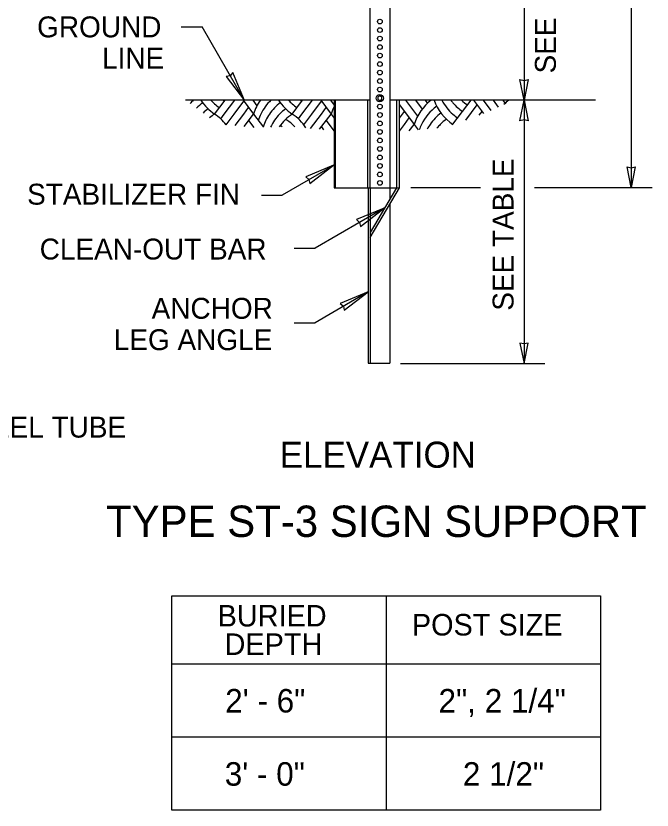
# Model space of a CAD drawing. Extents: x 99862 to 103680, y 99470 to 102076.
# Drawn here: x 101132 to 101618, y 100979 to 101587 of the extents above; entities that cross this region are included whole.
import ezdxf

# ---------------------------------------------------------------- set-up
doc = ezdxf.new("R2010")
doc.units = 0
for name, color, linetype in [('Level 15', 7, 'Continuous'), ('Level 2', 7, 'Continuous'), ('Level 20', 7, 'Continuous'), ('Level 3', 7, 'Continuous'), ('Level 4', 7, 'Continuous'), ('Level 40', 7, 'Continuous'), ('Level 5', 7, 'Continuous'), ('Level 6', 7, 'Continuous')]:
    doc.layers.add(name, color=color, linetype=linetype)

msp = doc.modelspace()

# ---------------------------------------------------------------- linework, layer by layer
at = {"layer": 'Level 15'}
for p, q in [((101258, 101578.2), (101274, 101578.2)), ((101306.5, 101521.91), (101274, 101578.2)), ((101375.06, 101472.43), (101335.38, 101449.51)), ((101319.38, 101449.51), (101335.38, 101449.51)), ((101413.43, 101439.5), (101360.5, 101408.8)), ((101344.5, 101408.8), (101360.5, 101408.8)), ((101400.98, 101375.33), (101360.5, 101351.82)), ((101344.5, 101351.82), (101360.5, 101351.82))]:
    msp.add_line(p, q, dxfattribs=at)
for points in [[(101602.31, 101944.46), (101602.31, 101455.34)], [(101520.31, 101815.74), (101520.31, 101522.09)], [(101520.31, 101522.09), (101520.31, 101320.46)], [(101433.72, 101455.34), (101487.14, 101455.34)], [(101528.31, 101455.34), (101618.31, 101455.34)], [(101425.95, 101320.46), (101536.31, 101320.46)]]:
    msp.add_lwpolyline(points, dxfattribs=at)
for points in [[(101306.5, 101521.91), (101297.67, 101543.17), (101295.61, 101540.77), (101292.5, 101540.19)], [(101520.31, 101522.09), (101517.23, 101537.81), (101520.31, 101537.09), (101523.4, 101537.81)], [(101520.31, 101522.09), (101523.4, 101506.37), (101520.31, 101507.09), (101517.23, 101506.37)], [(101374.65, 101472.39), (101353.39, 101463.56), (101355.8, 101461.5), (101356.37, 101458.39)], [(101602.31, 101455.34), (101599.23, 101471.06), (101602.31, 101470.34), (101605.4, 101471.06)], [(101413.43, 101439.5), (101392.17, 101430.67), (101394.58, 101428.61), (101395.15, 101425.5)], [(101400.98, 101375.33), (101379.71, 101366.5), (101382.12, 101364.45), (101382.7, 101361.33)], [(101520.31, 101320.51), (101523.4, 101336.23), (101520.31, 101335.51), (101517.23, 101336.23)]]:
    msp.add_lwpolyline(points, close=True, dxfattribs=at)
at = {"layer": 'Level 2'}
for points in [[(101402.69, 101522.06), (101402.69, 101660.51)], [(101417.79, 101660.51), (101417.79, 101521.95)], [(101402.69, 101454.42), (101402.69, 101522.09)], [(101417.79, 101521.85), (101417.79, 101454.64)]]:
    msp.add_lwpolyline(points, dxfattribs=at)
msp.add_lwpolyline([(101409.93, 101525.36), (101408.44, 101524.5), (101408.44, 101522.77), (101409.93, 101521.9), (101411.43, 101522.77), (101411.43, 101524.5)], close=True, dxfattribs=at)
msp.add_circle((101409.93, 101523.63), 2.77, dxfattribs=at)
at = {"layer": 'Level 3'}
for p, q in [((101400.98, 101454.91), (101400.98, 101320.78)), ((101402.65, 101454.91), (101402.65, 101320.78)), ((101417.74, 101454.91), (101417.74, 101446.29)), ((101417.74, 101442.33), (101417.74, 101320.78)), ((101400.98, 101320.78), (101402.65, 101320.78)), ((101402.65, 101320.78), (101417.74, 101320.78))]:
    msp.add_line(p, q, dxfattribs=at)
for centre in [(101410.06, 101582.27), (101410.06, 101575.77), (101410.06, 101569.27), (101410.06, 101562.77), (101410.06, 101556.27), (101410.06, 101549.77), (101410.06, 101543.27), (101410.06, 101536.77), (101410.06, 101530.27), (101410.06, 101517.27), (101410.06, 101510.77), (101410.06, 101504.27), (101410.06, 101497.77), (101410.06, 101491.27), (101410.06, 101484.77), (101410.06, 101478.27), (101410.06, 101471.77), (101410.06, 101465.27), (101410.06, 101458.77)]:
    msp.add_circle(centre, 1.8, dxfattribs=at)
at = {"layer": 'Level 4'}
for p, q in [((101375.06, 101522.09), (101375.06, 101454.91)), ((101375.77, 101521.97), (101375.77, 101454.91)), ((101400.88, 101454.91), (101400.88, 101521.97)), ((101422.81, 101522.09), (101422.81, 101454.91)), ((101424.95, 101454.91), (101424.95, 101522.09)), ((101423.82, 101454.91), (101424.95, 101454.91))]:
    msp.add_line(p, q, dxfattribs=at)
for points, degree in [([(101375.06, 101454.91), (101375.42, 101454.91), (101375.77, 101454.91)], 2), ([(101375.77, 101454.91), (101388.32, 101454.91), (101400.88, 101454.91), (101411.84, 101454.91), (101422.81, 101454.91), (101423.32, 101454.91), (101423.82, 101454.91)], 4)]:
    msp.add_open_spline(points, degree=degree, dxfattribs=at)
at = {"layer": 'Level 40'}
for p, q in [((101414.79, 101142.76), (101414.79, 100978.76)), ((101250.79, 101090.76), (101578.79, 101090.76)), ((101250.79, 101034.76), (101578.79, 101034.76))]:
    msp.add_line(p, q, dxfattribs=at)
msp.add_lwpolyline([(101250.79, 101142.76), (101578.79, 101142.76), (101578.79, 100978.76), (101250.79, 100978.76)], close=True, dxfattribs=at)
at = {"layer": 'Level 5'}
for p, q in [((101283.62, 101511.49), (101291.57, 101522.09)), ((101291.04, 101511.49), (101298.99, 101522.09)), ((101298.47, 101511.49), (101305.89, 101521.39)), ((101305.37, 101522.09), (101313.32, 101511.49)), ((101312.79, 101522.09), (101315.99, 101517.82)), ((101343.02, 101511.49), (101350.97, 101522.09)), ((101350.44, 101511.49), (101358.39, 101522.09)), ((101357.87, 101511.49), (101365.29, 101521.39)), ((101364.77, 101522.09), (101372.71, 101511.49)), ((101372.19, 101522.09), (101375.06, 101518.26)), ((101429.77, 101522.09), (101438.91, 101509.9)), ((101437.19, 101522.09), (101442.35, 101515.21)), ((101444.61, 101522.09), (101446.43, 101519.67)), ((101465.97, 101503.63), (101479.82, 101522.09)), ((101481.74, 101522.09), (101489.39, 101511.89)), ((101489.16, 101522.09), (101495.04, 101514.26)), ((101496.59, 101522.09), (101500.6, 101516.74)), ((101504.01, 101522.09), (101505.82, 101519.67)), ((101305.89, 101511.49), (101309.61, 101516.44)), ((101365.29, 101511.49), (101369, 101516.44)), ((101424.95, 101518.61), (101436.23, 101503.57)), ((101424.95, 101518.23), (101425.1, 101518.42)), ((101475.78, 101506.8), (101484.49, 101518.42)), ((101288.27, 101507.8), (101291.04, 101511.49)), ((101292.35, 101503.33), (101298.47, 101511.49)), ((101299.27, 101502.66), (101305.89, 101511.49)), ((101306.19, 101501.98), (101313.32, 101511.49)), ((101313.32, 101511.49), (101320.92, 101501.35)), ((101347.67, 101507.8), (101350.44, 101511.49)), ((101351.75, 101503.33), (101357.87, 101511.49)), ((101357.07, 101500.53), (101365.29, 101511.49)), ((101363.96, 101499.81), (101372.71, 101511.49)), ((101372.71, 101511.49), (101375.06, 101508.36)), ((101424.95, 101508.33), (101428.81, 101513.47)), ((101428.81, 101503.57), (101432.52, 101508.52)), ((101486.02, 101510.55), (101488.2, 101513.47)), ((101309.61, 101506.54), (101313.57, 101501.26)), ((101369, 101506.54), (101374.91, 101498.67)), ((101424.95, 101498.43), (101428.81, 101503.57)), ((101432.58, 101498.7), (101436.23, 101503.57)), ((101436.23, 101503.57), (101439.42, 101499.32)), ((101365.29, 101501.59), (101366.85, 101499.51))]:
    msp.add_line(p, q, dxfattribs=at)
for points in [[(101402.69, 101522.09), (101261.37, 101522.09)], [(101574.9, 101522.09), (101417.81, 101522.09)]]:
    msp.add_lwpolyline(points, dxfattribs=at)
for centre, start, end in [((101293.44, 101495.15), 134.20359, 139.54123), ((101297.16, 101490.2), 127.1006, 136.78764), ((101304.58, 101542.68), 213.22467, 236.09639), ((101308.29, 101547.63), 222.81589, 228.95992), ((101312.01, 101552.58), 234.22962, 236.09639), ((101349.13, 101500.1), 144.18673, 162.3566), ((101352.84, 101495.15), 134.20359, 154.2266), ((101356.55, 101490.2), 127.1006, 145.49109), ((101363.98, 101542.68), 213.22467, 236.09639), ((101367.69, 101547.63), 222.81589, 228.95992), ((101371.4, 101552.58), 234.22962, 236.09639), ((101472.04, 101492.18), 127.25098, 162.3566), ((101486.89, 101534.76), 199.69891, 236.0125), ((101490.6, 101539.71), 207.95634, 228.95992), ((101494.32, 101544.66), 216.90715, 220.94161), ((101494.31, 101544.66), 220.94154, 236.09639), ((101498.03, 101549.61), 227.07462, 236.09639), ((101531.44, 101492.18), 127.25098, 134.97567), ((101546.29, 101534.76), 199.69891, 200.13174), ((101300.87, 101485.25), 126.331, 134.01775), ((101308.29, 101547.63), 228.95986, 236.09639), ((101360.27, 101485.25), 126.331, 135.71278), ((101367.69, 101547.63), 228.95986, 236.09639), ((101408.52, 101500.1), 152.92754, 162.3566), ((101475.75, 101487.23), 126.30625, 154.2266), ((101304.58, 101480.3), 123.90361, 131.22462), ((101262.66, 101480.3), 37.78921, 56.09634), ((101352.84, 101495.15), 154.22654, 162.3566), ((101356.55, 101490.2), 145.49102, 162.3566), ((101360.27, 101485.25), 135.71269, 154.40628), ((101363.98, 101480.3), 123.90361, 145.3805), ((101322.06, 101480.3), 33.25737, 56.09634), ((101479.47, 101482.28), 127.1006, 145.49109), ((101490.6, 101539.71), 228.95986, 236.09639), ((101314.63, 101470.4), 56.42141, 59.30215), ((101318.34, 101475.35), 48.95968, 58.54646), ((101318.34, 101475.35), 44.71841, 48.95975), ((101475.75, 101487.23), 154.22654, 161.11875), ((101479.47, 101482.28), 145.49102, 151.96896), ((101483.18, 101477.33), 135.71269, 141.73037), ((101483.18, 101477.33), 126.331, 135.71278)]:
    msp.add_arc(centre, 37.58, start, end, dxfattribs=at)
at = {"layer": 'Level 6'}
for p, q in [((101422.83, 101454.91), (101402.65, 101420.71)), ((101402.65, 101417.11), (101424.95, 101454.91))]:
    msp.add_line(p, q, dxfattribs=at)

# ---------------------------------------------------------------- texts
at = {"layer": 'Level 20'}
for s, height, p in [('GROUND', 16, (101147.83, 101570.2)), ('LINE', 16, (101197.5, 101546.2)), ('SQUARE, 12-GAGE STEEL TUBE', 16, (100884.21, 101263.88)), ('ELEVATION', 20, (101333.41, 101240.78)), ('TYPE ST-3 SIGN SUPPORT', 24, (101200.52, 101187.83)), ('BURIED', 16.5, (101285.93, 101119.29)), ('POST SIZE', 16.5, (101434.51, 101112.39)), ('DEPTH', 16.5, (101291.22, 101097.5)), ('2\' - 6"', 18, (101291.72, 101053.45)), ('2", 2 1/4"', 18, (101454.94, 101053.45)), ('3\' - 0"', 18, (101291.38, 100997.45)), ('2 1/2"', 18, (101473.55, 100997.45))]:
    msp.add_text(s, height=height, dxfattribs=at).set_placement(p)
for s, rotation, p in [('SEE ', 90, (101544.68, 101542.59)), ('SEE TABLE', 90, (101512.31, 101360.98)), ('STABILIZER FIN', 359.99999, (101140.16, 101442.14)), ('CLEAN-OUT BAR', 359.99999, (101149.79, 101400.16)), ('ANCHOR', 359.99999, (101235.43, 101354.81)), ('LEG ANGLE', 359.99999, (101206.48, 101330.81))]:
    msp.add_text(s, height=16, rotation=rotation, dxfattribs=at).set_placement(p)

doc.saveas('drawing.dxf')
